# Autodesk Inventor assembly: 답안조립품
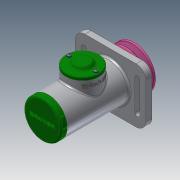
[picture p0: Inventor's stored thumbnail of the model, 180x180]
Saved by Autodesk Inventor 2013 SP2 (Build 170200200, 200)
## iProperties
Created: 2021-07
Part Number: 답안조립품
Document SubType Name: Assembly
Designer: kumcom17
Author: kumcom17
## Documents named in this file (20)
- C:\Users\kumcom17\Desktop\710706V1021\답안조립품.iam
- C:\Users\kumcom17\Desktop\710706V1021\본체.ipt
- C:\Users\kumcom17\Desktop\710706V1021\V-벨트풀리.ipt
- C:\Users\kumcom17\Desktop\710706V1021\너트 M10.ipt
- C:\Users\kumcom17\Desktop\710706V1021\멈춤링 15 x 1.ipt
- C:\Users\kumcom17\Desktop\710706V1021\멈춤링 35 x 1.6.ipt
- C:\Users\kumcom17\Desktop\710706V1021\베어링 15 x 35 x 11.ipt
- C:\Users\kumcom17\Desktop\710706V1021\볼트 M4 x 10.ipt
- C:\Users\kumcom17\Desktop\710706V1021\부시1.ipt
- C:\Users\kumcom17\Desktop\710706V1021\부시2.ipt
- C:\Users\kumcom17\Desktop\710706V1021\사이드 커버.ipt
- 사이드 커버.ipt
- C:\Users\kumcom17\Desktop\710706V1021\십자볼트 M3 x 10.ipt
- C:\Users\kumcom17\Desktop\710706V1021\오일 실 15 25 7.ipt
- C:\Users\kumcom17\Desktop\710706V1021\와셔 3 x 6.ipt
- C:\Users\kumcom17\Desktop\710706V1021\와셔 4 x 16.ipt
- C:\Users\kumcom17\Desktop\710706V1021\와셔 10 x 21.ipt
- C:\Users\kumcom17\Desktop\710706V1021\축.ipt
- C:\Users\kumcom17\Desktop\710706V1021\키 4 x 4 x 18.ipt
- C:\Users\kumcom17\Desktop\710706V1021\탑 커버.ipt
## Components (2 placed, 2 different names)
1. V-벨트풀리:1
2. ISO 4017 M4 x 10:1
